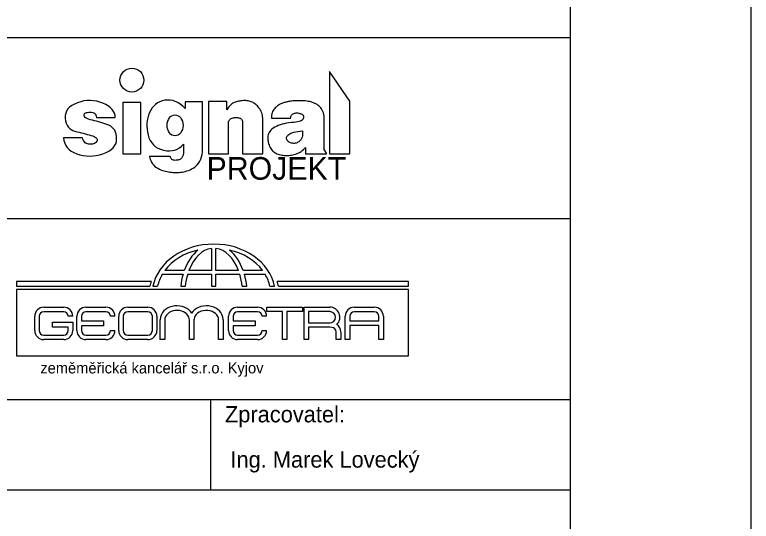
# Model space of a CAD drawing. Extents: x 2583 to 4283, y -3400 to -2956.
# Drawn here: x 3456.4 to 3537.7, y -3301.1 to -3245.1 of the extents above; entities that cross this region are included whole.
import ezdxf

# ---------------------------------------------------------------- set-up
doc = ezdxf.new("R2010")
doc.units = 0
for name, color, linetype in [('Default', 7, 'Continuous'), ('Vrstva 1', 7, 'Continuous'), ('Vrstva 11', 7, 'Continuous'), ('Vrstva 17', 7, 'Continuous'), ('Vrstva 6', 7, 'Continuous')]:
    doc.layers.add(name, color=color, linetype=linetype)

msp = doc.modelspace()

# ---------------------------------------------------------------- linework, layer by layer
at = {"layer": 'Default'}
msp.add_lwpolyline([(3327.684, -3399.617), (3537.684, -3399.617), (3537.684, -3102.617), (3327.684, -3102.617)], close=True, dxfattribs=at)
at = {"layer": 'Vrstva 1'}
msp.add_lwpolyline([(3347.684, -3122.617), (3517.684, -3122.617), (3517.684, -3382.617), (3347.684, -3382.617)], close=True, dxfattribs=at)
at = {"layer": 'Vrstva 11'}
for points in [[(3493.348, -3260.496), (3493.348, -3254.656), (3491.108, -3251.376), (3491.108, -3260.496), (3493.348, -3260.496)], [(3464.62, -3260.731), (3464.982, -3260.714), (3465.348, -3260.666), (3465.719, -3260.587), (3466.095, -3260.477), (3466.45, -3260.341), (3466.758, -3260.185), (3467.019, -3260.009), (3467.233, -3259.813), (3467.4, -3259.597), (3467.521, -3259.361), (3467.594, -3259.105), (3467.621, -3258.829), (3467.61, -3258.556), (3467.572, -3258.307), (3467.506, -3258.083), (3467.412, -3257.883), (3467.291, -3257.708), (3467.141, -3257.558), (3466.964, -3257.433), (3466.76, -3257.332), (3466.54, -3257.246), (3466.318, -3257.164), (3466.094, -3257.087), (3465.868, -3257.014), (3465.639, -3256.946), (3465.408, -3256.881), (3465.174, -3256.822), (3464.939, -3256.766), (3464.717, -3256.711), (3464.526, -3256.652), (3464.365, -3256.589), (3464.235, -3256.522), (3464.135, -3256.451), (3464.065, -3256.376), (3464.026, -3256.297), (3464.018, -3256.214), (3464.034, -3256.134), (3464.071, -3256.065), (3464.127, -3256.007), (3464.203, -3255.96), (3464.299, -3255.924), (3464.414, -3255.898), (3464.55, -3255.884), (3464.705, -3255.88), (3464.86, -3255.891), (3464.996, -3255.92), (3465.111, -3255.967), (3465.205, -3256.033), (3465.28, -3256.117), (3465.335, -3256.219), (3465.369, -3256.339), (3465.384, -3256.478), (3467.463, -3256.478), (3467.444, -3256.236), (3467.381, -3256.007), (3467.276, -3255.789), (3467.128, -3255.585), (3466.938, -3255.394), (3466.704, -3255.215), (3466.427, -3255.049), (3466.108, -3254.895), (3465.766, -3254.766), (3465.421, -3254.671), (3465.073, -3254.612), (3464.723, -3254.587), (3464.37, -3254.597), (3464.014, -3254.642), (3463.656, -3254.721), (3463.295, -3254.836), (3462.957, -3254.978), (3462.668, -3255.141), (3462.427, -3255.324), (3462.235, -3255.528), (3462.091, -3255.753), (3461.997, -3255.997), (3461.95, -3256.263), (3461.953, -3256.549), (3461.992, -3256.83), (3462.058, -3257.082), (3462.151, -3257.305), (3462.269, -3257.497), (3462.414, -3257.661), (3462.585, -3257.795), (3462.782, -3257.899), (3463.005, -3257.974), (3463.24, -3258.034), (3463.471, -3258.093), (3463.699, -3258.152), (3463.923, -3258.211), (3464.143, -3258.27), (3464.36, -3258.328), (3464.573, -3258.386), (3464.783, -3258.444), (3464.975, -3258.504), (3465.136, -3258.568), (3465.267, -3258.637), (3465.366, -3258.711), (3465.435, -3258.789), (3465.473, -3258.871), (3465.48, -3258.958), (3465.456, -3259.049), (3465.409, -3259.137), (3465.348, -3259.214), (3465.273, -3259.278), (3465.183, -3259.331), (3465.079, -3259.373), (3464.96, -3259.403), (3464.827, -3259.421), (3464.68, -3259.428), (3464.532, -3259.418), (3464.396, -3259.384), (3464.272, -3259.329), (3464.161, -3259.25), (3464.062, -3259.149), (3463.976, -3259.025), (3463.902, -3258.879), (3463.84, -3258.71), (3461.76, -3258.71), (3461.804, -3259.017), (3461.887, -3259.299), (3462.01, -3259.557), (3462.173, -3259.791), (3462.375, -3260), (3462.617, -3260.185), (3462.898, -3260.346), (3463.219, -3260.483), (3463.562, -3260.592), (3463.91, -3260.669), (3464.263, -3260.716), (3464.62, -3260.731)], [(3470.308, -3260.496), (3470.308, -3254.816), (3468.308, -3254.816), (3468.308, -3260.496), (3470.308, -3260.496)], [(3474.168, -3262.538), (3474.336, -3262.534), (3474.506, -3262.526), (3474.678, -3262.512), (3474.852, -3262.494), (3475.026, -3262.467), (3475.2, -3262.428), (3475.374, -3262.377), (3475.547, -3262.314), (3475.72, -3262.238), (3475.893, -3262.15), (3476.066, -3262.051), (3476.238, -3261.939), (3476.402, -3261.809), (3476.551, -3261.656), (3476.683, -3261.481), (3476.8, -3261.282), (3476.901, -3261.06), (3476.986, -3260.815), (3477.055, -3260.547), (3477.108, -3260.256), (3477.108, -3254.736), (3475.188, -3254.736), (3475.188, -3255.456), (3474.922, -3255.201), (3474.652, -3254.988), (3474.377, -3254.816), (3474.098, -3254.685), (3473.815, -3254.595), (3473.528, -3254.546), (3473.236, -3254.539), (3472.94, -3254.572), (3472.653, -3254.64), (3472.388, -3254.737), (3472.144, -3254.863), (3471.922, -3255.016), (3471.722, -3255.199), (3471.544, -3255.41), (3471.388, -3255.649), (3471.253, -3255.917), (3471.142, -3256.203), (3471.057, -3256.496), (3470.998, -3256.796), (3470.965, -3257.103), (3470.958, -3257.418), (3470.977, -3257.74), (3471.022, -3258.068), (3471.093, -3258.405), (3471.193, -3258.728), (3471.325, -3259.019), (3471.491, -3259.277), (3471.689, -3259.502), (3471.92, -3259.695), (3472.183, -3259.855), (3472.479, -3259.982), (3472.808, -3260.077), (3473.144, -3260.135), (3473.463, -3260.152), (3473.763, -3260.129), (3474.046, -3260.065), (3474.312, -3259.96), (3474.559, -3259.815), (3474.789, -3259.628), (3475, -3259.402), (3475, -3260.478), (3474.982, -3260.566), (3474.959, -3260.648), (3474.931, -3260.723), (3474.899, -3260.794), (3474.863, -3260.858), (3474.822, -3260.917), (3474.776, -3260.97), (3474.726, -3261.017), (3474.67, -3261.059), (3474.608, -3261.095), (3474.538, -3261.126), (3474.461, -3261.152), (3474.377, -3261.172), (3474.286, -3261.187), (3474.188, -3261.196), (3474.083, -3261.2), (3473.979, -3261.195), (3473.886, -3261.176), (3473.802, -3261.144), (3473.729, -3261.099), (3473.666, -3261.041), (3473.614, -3260.969), (3473.571, -3260.884), (3473.539, -3260.786), (3471.232, -3260.786), (3471.301, -3261.014), (3471.384, -3261.223), (3471.481, -3261.413), (3471.592, -3261.584), (3471.717, -3261.737), (3471.855, -3261.871), (3472.008, -3261.986), (3472.174, -3262.082), (3472.346, -3262.165), (3472.517, -3262.239), (3472.686, -3262.305), (3472.854, -3262.362), (3473.02, -3262.41), (3473.185, -3262.45), (3473.348, -3262.481), (3473.51, -3262.504), (3473.672, -3262.52), (3473.835, -3262.531), (3474.001, -3262.537), (3474.168, -3262.538)], [(3483.748, -3260.496), (3483.748, -3256.696), (3483.745, -3256.526), (3483.731, -3256.363), (3483.706, -3256.206), (3483.671, -3256.056), (3483.625, -3255.912), (3483.568, -3255.776), (3483.5, -3255.645), (3483.421, -3255.522), (3483.336, -3255.405), (3483.249, -3255.297), (3483.16, -3255.197), (3483.069, -3255.106), (3482.976, -3255.022), (3482.881, -3254.947), (3482.784, -3254.88), (3482.685, -3254.821), (3482.583, -3254.77), (3482.477, -3254.725), (3482.366, -3254.688), (3482.251, -3254.658), (3482.131, -3254.634), (3482.008, -3254.617), (3481.88, -3254.608), (3481.748, -3254.605), (3481.614, -3254.608), (3481.481, -3254.616), (3481.35, -3254.629), (3481.22, -3254.647), (3481.091, -3254.67), (3480.963, -3254.698), (3480.836, -3254.731), (3480.711, -3254.769), (3480.587, -3254.817), (3480.466, -3254.882), (3480.347, -3254.963), (3480.231, -3255.061), (3480.116, -3255.175), (3480.005, -3255.305), (3479.895, -3255.452), (3479.788, -3255.616), (3479.788, -3254.696), (3477.748, -3254.696), (3477.748, -3260.496), (3479.988, -3260.496), (3479.988, -3256.936), (3480.023, -3256.845), (3480.067, -3256.764), (3480.121, -3256.693), (3480.186, -3256.632), (3480.26, -3256.581), (3480.344, -3256.54), (3480.438, -3256.509), (3480.542, -3256.488), (3480.648, -3256.475), (3480.749, -3256.468), (3480.844, -3256.467), (3480.934, -3256.472), (3481.019, -3256.484), (3481.099, -3256.501), (3481.173, -3256.525), (3481.242, -3256.555), (3481.305, -3256.589), (3481.359, -3256.628), (3481.404, -3256.67), (3481.442, -3256.716), (3481.471, -3256.765), (3481.492, -3256.818), (3481.504, -3256.875), (3481.508, -3256.936), (3481.508, -3260.496), (3483.748, -3260.496)], [(3486.311, -3260.66), (3486.473, -3260.657), (3486.63, -3260.648), (3486.784, -3260.634), (3486.933, -3260.614), (3487.077, -3260.588), (3487.217, -3260.556), (3487.353, -3260.519), (3487.485, -3260.476), (3487.614, -3260.425), (3487.741, -3260.363), (3487.866, -3260.292), (3487.99, -3260.209), (3488.112, -3260.116), (3488.232, -3260.013), (3488.351, -3259.9), (3488.468, -3259.776), (3488.468, -3260.496), (3490.788, -3260.496), (3490.788, -3260.416), (3490.548, -3260.016), (3490.548, -3256.536), (3490.522, -3256.331), (3490.486, -3256.141), (3490.441, -3255.965), (3490.386, -3255.804), (3490.321, -3255.657), (3490.247, -3255.525), (3490.164, -3255.407), (3490.071, -3255.304), (3489.97, -3255.211), (3489.862, -3255.125), (3489.749, -3255.047), (3489.629, -3254.975), (3489.503, -3254.91), (3489.37, -3254.852), (3489.232, -3254.8), (3489.087, -3254.756), (3488.935, -3254.718), (3488.776, -3254.686), (3488.609, -3254.66), (3488.436, -3254.639), (3488.255, -3254.624), (3488.067, -3254.615), (3487.872, -3254.611), (3487.67, -3254.613), (3487.471, -3254.619), (3487.287, -3254.627), (3487.118, -3254.638), (3486.963, -3254.651), (3486.823, -3254.666), (3486.698, -3254.683), (3486.588, -3254.702), (3486.492, -3254.724), (3486.404, -3254.748), (3486.314, -3254.773), (3486.224, -3254.801), (3486.134, -3254.83), (3486.042, -3254.862), (3485.95, -3254.895), (3485.857, -3254.931), (3485.764, -3254.968), (3485.671, -3255.01), (3485.578, -3255.058), (3485.487, -3255.114), (3485.397, -3255.176), (3485.308, -3255.245), (3485.22, -3255.321), (3485.132, -3255.403), (3485.046, -3255.493), (3484.966, -3255.59), (3484.897, -3255.697), (3484.838, -3255.814), (3484.791, -3255.939), (3484.754, -3256.074), (3484.728, -3256.219), (3484.713, -3256.373), (3484.708, -3256.536), (3486.828, -3256.536), (3486.844, -3256.439), (3486.868, -3256.352), (3486.901, -3256.274), (3486.942, -3256.205), (3486.992, -3256.146), (3487.051, -3256.095), (3487.118, -3256.054), (3487.194, -3256.021), (3487.275, -3255.997), (3487.356, -3255.979), (3487.437, -3255.968), (3487.519, -3255.963), (3487.602, -3255.965), (3487.685, -3255.973), (3487.769, -3255.988), (3487.853, -3256.009), (3487.933, -3256.035), (3488.005, -3256.063), (3488.067, -3256.092), (3488.121, -3256.124), (3488.166, -3256.159), (3488.203, -3256.195), (3488.23, -3256.233), (3488.249, -3256.274), (3488.26, -3256.317), (3488.265, -3256.363), (3488.264, -3256.411), (3488.257, -3256.463), (3488.243, -3256.517), (3488.223, -3256.574), (3488.197, -3256.634), (3488.165, -3256.696), (3488.114, -3256.757), (3488.033, -3256.813), (3487.921, -3256.864), (3487.78, -3256.909), (3487.608, -3256.949), (3487.405, -3256.984), (3487.173, -3257.014), (3486.91, -3257.038), (3486.638, -3257.064), (3486.378, -3257.102), (3486.131, -3257.15), (3485.896, -3257.208), (3485.673, -3257.277), (3485.463, -3257.357), (3485.265, -3257.447), (3485.079, -3257.547), (3484.91, -3257.656), (3484.761, -3257.768), (3484.634, -3257.885), (3484.527, -3258.007), (3484.442, -3258.133), (3484.377, -3258.264), (3484.333, -3258.399), (3484.31, -3258.539), (3484.302, -3258.68), (3484.303, -3258.82), (3484.313, -3258.959), (3484.332, -3259.097), (3484.36, -3259.234), (3484.397, -3259.369), (3484.443, -3259.504), (3484.498, -3259.637), (3484.561, -3259.765), (3484.631, -3259.884), (3484.708, -3259.995), (3484.791, -3260.096), (3484.882, -3260.189), (3484.98, -3260.273), (3485.084, -3260.347), (3485.196, -3260.413), (3485.314, -3260.471), (3485.438, -3260.521), (3485.568, -3260.564), (3485.704, -3260.598), (3485.847, -3260.625), (3485.995, -3260.644), (3486.15, -3260.656), (3486.311, -3260.66)], [(3487.027, -3259.315), (3486.924, -3259.295), (3486.829, -3259.267), (3486.742, -3259.231), (3486.663, -3259.187), (3486.593, -3259.136), (3486.53, -3259.077), (3486.475, -3259.01), (3486.428, -3258.935), (3486.394, -3258.858), (3486.376, -3258.781), (3486.375, -3258.705), (3486.39, -3258.63), (3486.423, -3258.555), (3486.472, -3258.482), (3486.538, -3258.41), (3486.62, -3258.338), (3486.724, -3258.27), (3486.852, -3258.207), (3487.006, -3258.149), (3487.185, -3258.097), (3487.389, -3258.05), (3487.619, -3258.008), (3487.873, -3257.971), (3488.153, -3257.94), (3488.157, -3258.139), (3488.149, -3258.321), (3488.127, -3258.487), (3488.092, -3258.636), (3488.045, -3258.77), (3487.984, -3258.887), (3487.911, -3258.989), (3487.825, -3259.074), (3487.731, -3259.145), (3487.636, -3259.205), (3487.539, -3259.252), (3487.44, -3259.288), (3487.339, -3259.313), (3487.237, -3259.325), (3487.133, -3259.326), (3487.027, -3259.315)]]:
    msp.add_lwpolyline(points, dxfattribs=at)
msp.add_circle((3469.308, -3252.336), 1.32, dxfattribs=at)
msp.add_ellipse((3474.068, -3257.336), major_axis=(0, 1.16), ratio=0.758621, dxfattribs=at)
at = {"layer": 'Vrstva 17'}
for p, q in [((3478.079, -3270.929), (3478.079, -3273.375)), ((3478.586, -3273.375), (3478.586, -3270.927)), ((3475.085, -3273.375), (3472.94, -3273.375)), ((3478.079, -3273.375), (3475.602, -3273.375)), ((3481.08, -3273.375), (3478.586, -3273.375)), ((3483.742, -3273.375), (3481.597, -3273.375)), ((3472.665, -3273.787), (3474.953, -3273.787)), ((3475.463, -3273.787), (3478.079, -3273.787)), ((3478.079, -3273.787), (3478.079, -3275.107)), ((3478.586, -3275.107), (3478.586, -3273.787)), ((3478.586, -3273.787), (3481.22, -3273.787)), ((3481.73, -3273.787), (3484.017, -3273.787)), ((3471.434, -3274.576), (3456.554, -3274.576)), ((3456.554, -3274.576), (3456.554, -3275.107)), ((3456.554, -3275.107), (3471.297, -3275.107)), ((3471.622, -3275.107), (3472.139, -3275.107)), ((3474.696, -3275.107), (3475.196, -3275.107)), ((3478.079, -3275.107), (3478.586, -3275.107)), ((3481.487, -3275.107), (3481.987, -3275.107)), ((3484.543, -3275.107), (3485.06, -3275.107)), ((3499.832, -3274.576), (3485.354, -3274.576)), ((3485.492, -3275.107), (3499.832, -3275.107)), ((3499.832, -3275.107), (3499.832, -3274.576)), ((3499.831, -3275.451), (3456.548, -3275.451)), ((3456.548, -3275.451), (3456.548, -3282.789)), ((3499.831, -3282.789), (3499.831, -3275.451)), ((3459.573, -3277.417), (3461.783, -3277.417)), ((3464.229, -3277.417), (3466.44, -3277.417)), ((3468.853, -3277.417), (3471.063, -3277.417)), ((3480.971, -3277.417), (3483.182, -3277.417)), ((3488.309, -3277.417), (3491.153, -3277.417)), ((3493.857, -3277.417), (3496.068, -3277.417)), ((3458.575, -3280.001), (3458.575, -3278.415)), ((3459.074, -3278.415), (3459.074, -3280.001)), ((3461.783, -3277.916), (3459.573, -3277.916)), ((3462.781, -3278.415), (3462.282, -3278.415)), ((3463.231, -3280.001), (3463.231, -3278.415)), ((3463.73, -3278.415), (3463.73, -3278.926)), ((3466.44, -3277.916), (3464.229, -3277.916)), ((3467.437, -3278.415), (3466.939, -3278.415)), ((3467.855, -3280.001), (3467.855, -3278.415)), ((3468.354, -3278.415), (3468.354, -3280.001)), ((3471.063, -3277.916), (3468.853, -3277.916)), ((3471.563, -3280.001), (3471.563, -3278.415)), ((3472.061, -3278.415), (3472.061, -3280.001)), ((3479.974, -3280.001), (3479.974, -3278.415)), ((3480.472, -3278.415), (3480.472, -3278.926)), ((3483.182, -3277.916), (3480.971, -3277.916)), ((3484.18, -3278.415), (3483.681, -3278.415)), ((3485.914, -3280.999), (3485.914, -3277.904)), ((3486.418, -3277.904), (3486.418, -3280.999)), ((3491.153, -3277.906), (3488.813, -3277.906)), ((3488.813, -3277.906), (3488.813, -3279.156)), ((3492.859, -3280.999), (3492.859, -3278.415)), ((3493.358, -3278.415), (3493.358, -3278.924)), ((3496.068, -3277.916), (3493.857, -3277.916)), ((3496.567, -3278.924), (3496.567, -3278.415)), ((3497.065, -3278.415), (3497.065, -3280.999)), ((3460.548, -3279.623), (3460.548, -3279.079)), ((3460.548, -3279.079), (3462.781, -3279.079)), ((3462.781, -3279.079), (3462.781, -3280.001)), ((3463.73, -3278.926), (3466.173, -3278.926)), ((3466.173, -3278.926), (3466.173, -3279.47)), ((3472.434, -3280.999), (3472.434, -3278.814)), ((3472.934, -3278.814), (3472.934, -3280.999)), ((3475.654, -3280.999), (3475.654, -3278.814)), ((3476.154, -3278.814), (3476.154, -3280.999)), ((3478.873, -3280.999), (3478.873, -3278.814)), ((3479.373, -3278.814), (3479.373, -3280.999)), ((3480.472, -3278.926), (3482.915, -3278.926)), ((3482.915, -3278.926), (3482.915, -3279.47)), ((3488.813, -3279.156), (3491.153, -3279.156)), ((3493.358, -3278.924), (3496.567, -3278.924)), ((3462.282, -3279.623), (3460.548, -3279.623)), ((3462.282, -3280.001), (3462.282, -3279.623)), ((3466.173, -3279.47), (3463.73, -3279.47)), ((3463.73, -3279.47), (3463.73, -3280.001)), ((3466.939, -3280.001), (3467.437, -3280.001)), ((3482.915, -3279.47), (3480.472, -3279.47)), ((3480.472, -3279.47), (3480.472, -3280.001)), ((3483.681, -3280.001), (3484.18, -3280.001)), ((3491.153, -3279.645), (3488.813, -3279.645)), ((3491.367, -3279.649), (3491.153, -3279.645)), ((3491.866, -3280.999), (3491.866, -3280.148)), ((3492.365, -3280.148), (3492.365, -3280.999)), ((3496.567, -3279.427), (3493.358, -3279.427)), ((3493.358, -3279.427), (3493.358, -3280.999)), ((3496.567, -3280.999), (3496.567, -3279.427)), ((3459.573, -3280.5), (3461.783, -3280.5)), ((3464.229, -3280.5), (3466.44, -3280.5)), ((3468.853, -3280.5), (3471.063, -3280.5)), ((3480.971, -3280.5), (3483.182, -3280.5)), ((3461.783, -3280.999), (3459.573, -3280.999)), ((3466.44, -3280.999), (3464.229, -3280.999)), ((3471.063, -3280.999), (3468.853, -3280.999)), ((3472.934, -3280.999), (3472.434, -3280.999)), ((3476.154, -3280.999), (3475.654, -3280.999)), ((3479.373, -3280.999), (3478.873, -3280.999)), ((3483.182, -3280.999), (3480.971, -3280.999)), ((3486.418, -3280.999), (3485.914, -3280.999)), ((3492.365, -3280.999), (3491.866, -3280.999)), ((3493.358, -3280.999), (3492.859, -3280.999)), ((3497.065, -3280.999), (3496.567, -3280.999)), ((3456.548, -3282.789), (3499.831, -3282.789))]:
    msp.add_line(p, q, dxfattribs=at)
for points in [[(3485.914, -3277.904), (3484.216, -3277.904), (3484.216, -3277.417), (3488.13, -3277.417)], [(3488.13, -3277.417), (3488.13, -3277.904), (3486.418, -3277.904)], [(3488.813, -3279.645), (3488.813, -3280.999), (3488.309, -3280.999), (3488.309, -3277.417)]]:
    msp.add_lwpolyline(points, dxfattribs=at)
for centre, radius, start, end in [((3459.573, -3278.415), 0.998, 90, 180), ((3461.783, -3278.415), 0.998, 360, 90), ((3464.229, -3278.415), 0.998, 90, 180), ((3466.44, -3278.415), 0.998, 360, 90), ((3468.853, -3278.415), 0.998, 90, 180), ((3471.063, -3278.415), 0.998, 360, 90), ((3480.971, -3278.415), 0.998, 90, 180), ((3483.182, -3278.415), 0.998, 360, 90), ((3491.153, -3278.531), 1.114, 314.45734, 90), ((3493.857, -3278.415), 0.998, 90, 180), ((3496.068, -3278.415), 0.998, 360, 90), ((3459.573, -3278.415), 0.499, 90, 180), ((3461.783, -3278.415), 0.499, 0, 90), ((3464.229, -3278.415), 0.499, 90, 180), ((3466.44, -3278.415), 0.499, 0, 90), ((3468.853, -3278.415), 0.499, 90, 180), ((3471.063, -3278.415), 0.499, 0, 90), ((3474.371, -3278.864), 1.938, 166.96576, 178.52091), ((3474.699, -3278.879), 0.957, 3.86486, 22.41569), ((3477.436, -3278.864), 1.938, 1.47909, 13.03424), ((3480.971, -3278.415), 0.499, 90, 180), ((3483.182, -3278.415), 0.499, 0, 90), ((3491.153, -3278.531), 0.625, 270, 90), ((3493.857, -3278.415), 0.499, 90, 180), ((3496.068, -3278.415), 0.499, 0, 90), ((3477.387, -3278.936), 1.238, 162.61388, 174.3506), ((3491.367, -3280.148), 0.998, 360, 55.44734), ((3459.573, -3280.001), 0.998, 180, 270), ((3459.573, -3280.001), 0.499, 180, 270), ((3461.783, -3280.001), 0.998, 270, 0), ((3461.783, -3280.001), 0.499, 270, 0), ((3464.229, -3280.001), 0.998, 180, 270), ((3464.229, -3280.001), 0.499, 180, 270), ((3466.44, -3280.001), 0.998, 270, 0), ((3466.44, -3280.001), 0.499, 270, 0), ((3468.853, -3280.001), 0.998, 180, 270), ((3468.853, -3280.001), 0.499, 180, 270), ((3471.063, -3280.001), 0.998, 270, 0), ((3471.063, -3280.001), 0.499, 270, 0), ((3480.971, -3280.001), 0.998, 180, 270), ((3480.971, -3280.001), 0.499, 180, 270), ((3483.182, -3280.001), 0.998, 270, 0), ((3483.182, -3280.001), 0.499, 270, 0), ((3491.367, -3280.148), 0.499, 0, 90)]:
    msp.add_arc(centre, radius, start, end, dxfattribs=at)
for centre, major_axis, ratio, start_param, end_param in [((3478.341, -3275.979), (-6.804, 0), 0.811768, 3.300239, 6.124539), ((3478.341, -3275.979), (-6.296, 0), 0.804826, 4.992897, 5.743383), ((3478.341, -3275.979), (0, 5.524), 0.668443, 0.491666, 1.079789), ((3478.341, -3275.979), (0, 5.067), 0.630136, 0.08224, 1.030995), ((3478.341, -3275.979), (0, 5.067), 0.630136, 5.252191, 6.206521), ((3478.341, -3275.979), (0, 5.524), 0.668443, 5.203397, 5.79152), ((3478.341, -3275.979), (-6.296, 0), 0.804826, 3.681394, 4.431881), ((3478.341, -3275.979), (-6.296, 0), 0.804826, 5.835664, 6.110118), ((3478.341, -3275.979), (0, 5.524), 0.668443, 1.16256, 1.41215), ((3478.341, -3275.979), (0, 5.067), 0.630136, 1.123275, 1.397729), ((3478.341, -3275.979), (0, 5.067), 0.630136, 4.885456, 5.159911), ((3478.341, -3275.979), (0, 5.524), 0.668443, 4.871035, 5.120625), ((3478.341, -3275.979), (-6.296, 0), 0.804826, 3.31466, 3.589114), ((3478.015, -3275.979), (-6.804, 0), 0.811768, 6.026233, 6.124539), ((3478.773, -3275.979), (-6.804, 0), 0.811768, 3.300239, 3.398545), ((3474.263, -3278.659), (1.805, 0), 0.766187, 0.429647, 2.97338), ((3474.288, -3278.814), (1.354, 0), 0.766187, 0.29376, 3.141593), ((3477.544, -3278.659), (-1.805, 0), 0.766187, 3.309805, 5.853538), ((3477.519, -3278.814), (-1.354, 0), 0.766187, 3.141593, 6.041607)]:
    msp.add_ellipse(centre, major_axis=major_axis, ratio=ratio, start_param=start_param, end_param=end_param, dxfattribs=at)
at = {"layer": 'Vrstva 6'}
for p, q in [((3347.684, -3267.617), (3517.684, -3267.617)), ((3347.684, -3287.617), (3517.684, -3287.617)), ((3478.034, -3297.617), (3478.034, -3287.617))]:
    msp.add_line(p, q, dxfattribs=at)
msp.add_lwpolyline([(3347.684, -3247.617), (3517.684, -3247.617), (3517.684, -3297.617), (3347.684, -3297.617)], close=True, dxfattribs=at)

# ---------------------------------------------------------------- texts
at = {"layer": 'Vrstva 11'}
msp.add_text('PROJEKT', height=2.5, dxfattribs=at).set_placement((3477.549, -3263.339))
at = {"layer": 'Vrstva 17'}
msp.add_text('zeměměřická kancelář s.r.o. Kyjov', height=1.20984, dxfattribs=at).set_placement((3459.199, -3284.738))
at = {"layer": 'Vrstva 6'}
for s, p in [('Zpracovatel:', (3479.58, -3290.143)), ('Ing. Marek Lovecký', (3480.181, -3295.143))]:
    msp.add_text(s, height=1.8, dxfattribs=at).set_placement(p)

doc.saveas('drawing.dxf')
